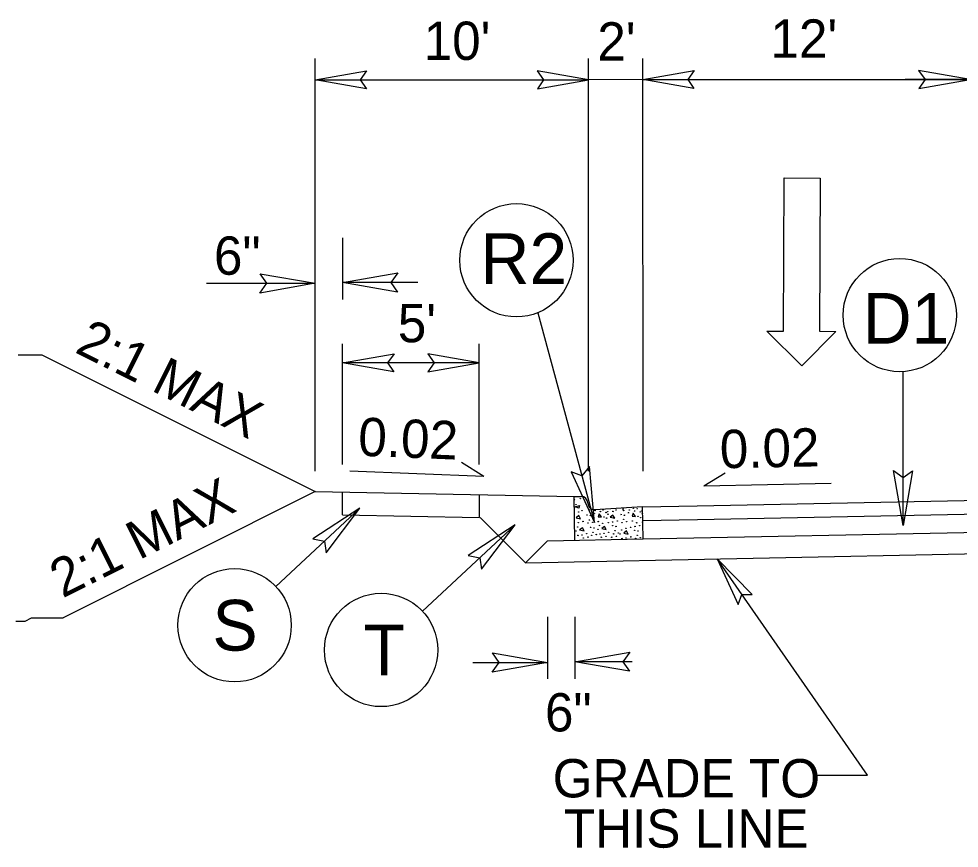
# Model space of a CAD drawing. Extents: x 1640342 to 1730599, y 538663 to 843747.
# Drawn here: x 1729967.52 to 1730001.9, y 539250.65 to 539280.96 of the extents above; entities that cross this region are included whole.
import ezdxf

# ---------------------------------------------------------------- set-up
doc = ezdxf.new("R2010")
doc.units = 0
for name, color, linetype in [('Default', 7, 'Continuous'), ('Prop Terminator CELL', 7, 'Continuous'), ('Typical Curb CELL', 7, 'Continuous'), ('Typical Hinge Slope Arterial CELL', 7, 'Continuous'), ('Typical Hinge Slope Interstate CELL', 7, 'Continuous'), ('Typical ID Circle CELL', 7, 'Continuous'), ('Typical Pavement Slope CELL', 7, 'Continuous'), ('Typical Pavement Slope Information CELL', 7, 'Continuous'), ('Typical Shoulder Slope CELL', 7, 'Continuous'), ('Typical Terminator CELL', 7, 'Continuous'), ('Typical Text General CELL', 7, 'Continuous'), ('Typical Text ID Circle CELL', 7, 'Continuous')]:
    doc.layers.add(name, color=color, linetype=linetype)

msp = doc.modelspace()

# ---------------------------------------------------------------- linework, layer by layer
at = {"layer": 'Default'}
for p, q in [((1729978.355, 539264.426), (1729978.355, 539279.516)), ((1729988.355, 539264.426), (1729988.355, 539279.516)), ((1729990.349, 539264.426), (1729990.333, 539279.516)), ((1729978.355, 539278.727), (1729988.356, 539278.727)), ((1729990.334, 539278.74), (1729988.356, 539278.727)), ((1729995.477, 539269.548), (1729995.507, 539275.144)), ((1729995.507, 539275.144), (1729996.826, 539275.137)), ((1729996.826, 539275.137), (1729996.796, 539269.541)), ((1729979.355, 539272.961), (1729979.355, 539270.701)), ((1729974.386, 539271.297), (1729978.355, 539271.297)), ((1729982.105, 539271.32), (1729979.355, 539271.32)), ((1729996.149, 539268.285), (1729994.877, 539269.551)), ((1729994.877, 539269.551), (1729995.477, 539269.548)), ((1729997.395, 539269.538), (1729996.149, 539268.285)), ((1729996.796, 539269.541), (1729997.395, 539269.538)), ((1729979.355, 539264.68), (1729979.355, 539269.082)), ((1729984.355, 539264.68), (1729984.355, 539269.082)), ((1729984.355, 539268.386), (1729979.355, 539268.386)), ((1729986.848, 539259.106), (1729986.848, 539256.846)), ((1729987.848, 539259.106), (1729987.848, 539256.846)), ((1729984.117, 539257.441), (1729986.848, 539257.441)), ((1729989.947, 539257.465), (1729987.848, 539257.465))]:
    msp.add_line(p, q, dxfattribs=at)
for points in [[(1729980.23, 539278.404), (1729978.355, 539278.727), (1729980.24, 539279.06), (1729980.001, 539278.727)], [(1729986.482, 539278.404), (1729988.356, 539278.727), (1729986.472, 539279.06), (1729986.711, 539278.727)], [(1729992.208, 539278.417), (1729990.334, 539278.74), (1729992.219, 539279.073), (1729991.979, 539278.74)], [(1730000.431, 539278.417), (1730002.305, 539278.74), (1730000.421, 539279.073), (1730000.66, 539278.74)], [(1729981.229, 539268.063), (1729979.355, 539268.386), (1729981.24, 539268.719), (1729981, 539268.386)], [(1729982.481, 539268.063), (1729984.355, 539268.386), (1729982.471, 539268.719), (1729982.71, 539268.386)]]:
    msp.add_lwpolyline(points, close=True, dxfattribs=at)
msp.add_lwpolyline([(1729990.334, 539278.74), (1730002.305, 539278.74), (1729999.934, 539278.749)], dxfattribs=at)
at = {"layer": 'Prop Terminator CELL'}
msp.add_lwpolyline([(1729994.335, 539259.922), (1729993.057, 539261.226), (1729993.823, 539259.555), (1729993.955, 539259.927)], close=True, dxfattribs=at)
at = {"layer": 'Typical Curb CELL'}
for p, q in [((1729987.823, 539263.502), (1729988.083, 539263.506)), ((1729987.848, 539261.908), (1729987.823, 539263.502)), ((1729987.865, 539263.124), (1729988.019, 539263.171)), ((1729988.003, 539263.081), (1729987.865, 539263.124)), ((1729988.019, 539263.171), (1729988.003, 539263.081)), ((1729988.326, 539263.259), (1729988.326, 539263.27)), ((1729990.327, 539263.124), (1729988.579, 539263.024)), ((1729990.345, 539261.958), (1729990.327, 539263.124)), ((1729987.996, 539262.808), (1729987.894, 539262.731)), ((1729987.894, 539262.731), (1729988.06, 539262.694)), ((1729988.06, 539262.694), (1729987.996, 539262.808)), ((1729988.736, 539262.875), (1729988.704, 539262.761)), ((1729988.704, 539262.761), (1729988.823, 539262.757)), ((1729988.823, 539262.757), (1729988.736, 539262.875)), ((1729989.244, 539262.827), (1729989.142, 539262.751)), ((1729989.142, 539262.751), (1729989.308, 539262.714)), ((1729989.308, 539262.714), (1729989.244, 539262.827)), ((1729989.984, 539262.895), (1729989.951, 539262.781)), ((1729989.951, 539262.781), (1729990.072, 539262.776)), ((1729990.072, 539262.776), (1729989.984, 539262.895)), ((1729988.129, 539262.359), (1729988.027, 539262.282)), ((1729988.193, 539262.245), (1729988.129, 539262.359)), ((1729988.935, 539262.415), (1729988.833, 539262.338)), ((1729988.999, 539262.301), (1729988.935, 539262.415)), ((1729988.027, 539262.282), (1729988.193, 539262.245)), ((1729988.833, 539262.338), (1729988.999, 539262.301)), ((1729989.74, 539262.246), (1729989.638, 539262.17)), ((1729989.638, 539262.17), (1729989.805, 539262.133)), ((1729989.805, 539262.133), (1729989.74, 539262.246))]:
    msp.add_line(p, q, dxfattribs=at)
for centre in [(1729987.838, 539263.392), (1729988.054, 539263.429), (1729987.892, 539263.21), (1729988.369, 539263.023), (1729989.617, 539263.043), (1729989.987, 539263.077), (1729990.13, 539263.062), (1729987.994, 539262.939), (1729988.113, 539262.991), (1729988.292, 539262.829), (1729988.387, 539262.973), (1729988.418, 539262.803), (1729988.565, 539262.891), (1729988.592, 539262.993), (1729988.786, 539262.956), (1729988.882, 539263.012), (1729988.915, 539262.759), (1729988.992, 539262.92), (1729989.011, 539262.715), (1729989.048, 539262.955), (1729989.066, 539262.858), (1729989.242, 539262.958), (1729989.361, 539263.01), (1729989.54, 539262.848), (1729989.635, 539262.993), (1729989.666, 539262.822), (1729989.813, 539262.91), (1729989.84, 539263.012), (1729990.034, 539262.976), (1729990.163, 539262.778), (1729990.24, 539262.939), (1729990.259, 539262.734), (1729990.296, 539262.974), (1729990.314, 539262.878), (1729987.951, 539262.39), (1729987.982, 539262.551), (1729988.153, 539262.593), (1729988.331, 539262.533), (1729988.386, 539262.648), (1729988.425, 539262.38), (1729988.501, 539262.564), (1729988.551, 539262.353), (1729988.706, 539262.59), (1729988.757, 539262.446), (1729988.867, 539262.524), (1729989.077, 539262.55), (1729989.23, 539262.57), (1729989.231, 539262.436), (1729989.357, 539262.41), (1729989.401, 539262.612), (1729989.579, 539262.552), (1729989.634, 539262.667), (1729989.717, 539262.346), (1729989.749, 539262.583), (1729989.888, 539262.377), (1729989.954, 539262.61), (1729990.054, 539262.411), (1729990.115, 539262.544), (1729990.225, 539262.443), (1729990.325, 539262.569), (1729987.897, 539262.246), (1729987.962, 539262.082), (1729988.116, 539262.102), (1729988.162, 539261.99), (1729988.286, 539262.144), (1729988.333, 539262.021), (1729988.464, 539262.084), (1729988.519, 539262.199), (1729988.635, 539262.115), (1729988.702, 539262.303), (1729988.768, 539262.138), (1729988.818, 539262.018), (1729988.921, 539262.158), (1729988.989, 539262.049), (1729989.092, 539262.2), (1729989.202, 539262.018), (1729989.27, 539262.14), (1729989.325, 539262.255), (1729989.373, 539262.049), (1729989.44, 539262.171), (1729989.508, 539262.134), (1729989.563, 539262.278), (1729989.727, 539261.989), (1729989.897, 539262.032), (1729990.036, 539262.268), (1729990.131, 539262.087), (1729990.162, 539262.241), (1729990.246, 539262.003), (1729989.573, 539261.969), (1729990.075, 539261.972)]:
    msp.add_circle(centre, 0.00801, dxfattribs=at)
for centre, start, end in [((1729988.087, 539263.266), 0.8814, 90.8814), ((1729988.566, 539263.263), 180.8814, 273.2659)]:
    msp.add_arc(centre, 0.239, start, end, dxfattribs=at)
at = {"layer": 'Typical Hinge Slope Arterial CELL'}
for p, q in [((1729968.363, 539268.687), (1729978.355, 539263.691)), ((1729978.355, 539263.691), (1729969.139, 539259.068))]:
    msp.add_line(p, q, dxfattribs=at)
msp.add_lwpolyline([(1729967.501, 539268.687), (1729967.871, 539268.687), (1729968.117, 539268.687), (1729968.363, 539268.687)], dxfattribs=at)
at = {"layer": 'Typical Hinge Slope Interstate CELL'}
msp.add_lwpolyline([(1729967.41, 539258.952), (1729967.756, 539258.952), (1729967.987, 539259.068), (1729968.332, 539259.068), (1729968.678, 539259.068), (1729969.139, 539259.068)], dxfattribs=at)
at = {"layer": 'Typical ID Circle CELL'}
for p, q in [((1729986.499, 539270.221), (1729988.57, 539262.554)), ((1729999.857, 539262.44), (1729999.857, 539268.066)), ((1729976.925, 539260.214), (1729979.989, 539263.076)), ((1729982.281, 539259.31), (1729985.665, 539262.471))]:
    msp.add_line(p, q, dxfattribs=at)
for centre in [(1729985.717, 539272.138), (1729999.732, 539270.133), (1729975.412, 539258.801), (1729980.768, 539257.897)]:
    msp.add_circle(centre, 2.071, dxfattribs=at)
at = {"layer": 'Typical Pavement Slope CELL'}
for p, q in [((1729992.327, 539263.164), (1730020.305, 539263.723)), ((1729990.327, 539263.124), (1729992.327, 539263.164)), ((1729992.337, 539262.664), (1730020.305, 539263.223)), ((1729984.395, 539262.737), (1729986.046, 539261.086)), ((1729990.337, 539262.624), (1729992.337, 539262.664)), ((1729990.345, 539261.958), (1730020.309, 539262.557)), ((1729986.848, 539261.888), (1729986.046, 539261.086)), ((1729986.046, 539261.086), (1730020.305, 539261.771)), ((1729986.848, 539261.888), (1729990.345, 539261.958))]:
    msp.add_line(p, q, dxfattribs=at)
at = {"layer": 'Typical Pavement Slope Information CELL'}
for p, q in [((1729984.52, 539264.239), (1729983.707, 539264.753)), ((1729984.52, 539264.239), (1729979.621, 539264.436)), ((1729992.566, 539263.901), (1729993.349, 539264.374)), ((1729992.566, 539263.901), (1729997.225, 539263.994))]:
    msp.add_line(p, q, dxfattribs=at)
at = {"layer": 'Typical Shoulder Slope CELL'}
for p, q in [((1729978.355, 539263.691), (1729987.823, 539263.502)), ((1729979.355, 539262.837), (1729979.355, 539263.672)), ((1729984.355, 539263.572), (1729984.355, 539262.737)), ((1729979.355, 539262.837), (1729984.355, 539262.737))]:
    msp.add_line(p, q, dxfattribs=at)
at = {"layer": 'Typical Terminator CELL'}
for p, q in [((1729998.553, 539253.323), (1729993.057, 539261.226)), ((1729996.643, 539253.323), (1729998.553, 539253.323))]:
    msp.add_line(p, q, dxfattribs=at)
for points in [[(1729976.348, 539271.642), (1729978.355, 539271.297), (1729976.336, 539270.94), (1729976.593, 539271.297)], [(1729981.363, 539270.975), (1729979.355, 539271.32), (1729981.374, 539271.677), (1729981.118, 539271.32)], [(1729987.713, 539264.402), (1729988.57, 539262.554), (1729988.388, 539264.596), (1729988.111, 539264.255)], [(1730000.203, 539264.447), (1729999.857, 539262.44), (1729999.5, 539264.459), (1729999.857, 539264.202)], [(1729978.758, 539261.453), (1729979.989, 539263.076), (1729978.27, 539261.959), (1729978.701, 539261.873)], [(1729984.434, 539260.848), (1729985.665, 539262.471), (1729983.946, 539261.354), (1729984.377, 539261.268)], [(1729984.84, 539257.787), (1729986.848, 539257.441), (1729984.829, 539257.085), (1729985.085, 539257.441)], [(1729989.855, 539257.12), (1729987.848, 539257.465), (1729989.867, 539257.822), (1729989.61, 539257.465)]]:
    msp.add_lwpolyline(points, close=True, dxfattribs=at)

# ---------------------------------------------------------------- texts
at = {"layer": 'Default'}
for s, p in [("10'", (1729982.325, 539279.459)), ('6"', (1729974.657, 539271.608)), ('6"', (1729986.76, 539254.92))]:
    msp.add_text(s, height=1.4, dxfattribs=at).set_placement(p)
msp.add_text("5'", height=1.4, rotation=360, dxfattribs=at).set_placement((1729981.379, 539269.141))
at = {"layer": 'Typical Hinge Slope Interstate CELL'}
for rotation, p in [(333.4354, (1729969.531, 539268.79)), (26.5646, (1729969.123, 539259.779))]:
    msp.add_text('2:1 MAX', height=1.4, rotation=rotation, dxfattribs=at).set_placement(p)
at = {"layer": 'Typical Pavement Slope Information CELL'}
for s, p in [("12'", (1729995.005, 539279.54)), ("2'", (1729988.673, 539279.435))]:
    msp.add_text(s, height=1.4, dxfattribs=at).set_placement(p)
for rotation, p in [(357.6997, (1729979.911, 539264.998)), (1.1457, (1729993.165, 539264.535))]:
    msp.add_text('0.02', height=1.4, rotation=rotation, dxfattribs=at).set_placement(p)
at = {"layer": 'Typical Text General CELL'}
for s, p in [('GRADE TO', (1729987.041, 539252.51)), ('THIS LINE', (1729987.449, 539250.674))]:
    msp.add_text(s, height=1.4, dxfattribs=at).set_placement(p)
at = {"layer": 'Typical Text ID Circle CELL'}
for s, height, p in [('R2', 1.8535, (1729984.404, 539271.269)), ('D1', 1.8535, (1729998.375, 539269.09)), ('S', 1.854, (1729974.601, 539257.874)), ('T', 1.854, (1729980.124, 539256.97))]:
    msp.add_text(s, height=height, dxfattribs=at).set_placement(p)

doc.saveas('drawing.dxf')
